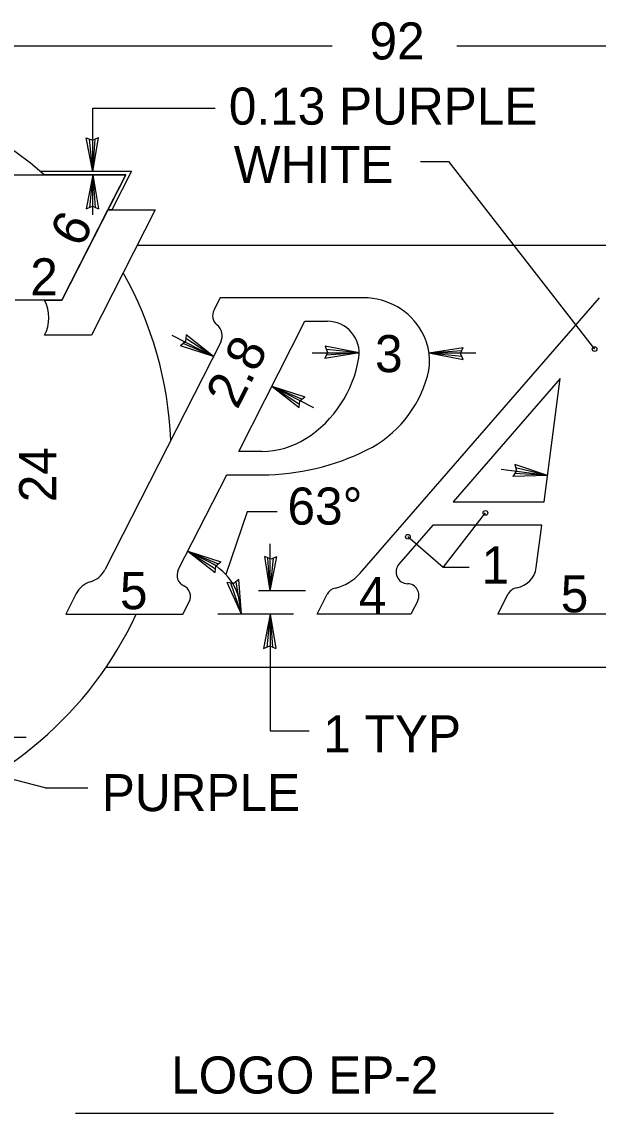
# Model space of a CAD drawing. Extents: x 10268197 to 10269179, y 2141503 to 2142677.
# Drawn here: x 10268694.59 to 10268707.32, y 2142243.22 to 2142267.31 of the extents above; entities that cross this region are included whole.
import ezdxf

# ---------------------------------------------------------------- set-up
doc = ezdxf.new("R2010")
doc.units = 0
for name, color, linetype in [('1', 7, 'Continuous'), ('21', 7, 'Continuous'), ('3', 7, 'Continuous'), ('52', 7, 'Continuous'), ('SOILS_SP83_SHP', 7, 'Continuous')]:
    doc.layers.add(name, color=color, linetype=linetype)

msp = doc.modelspace()

# ---------------------------------------------------------------- linework, layer by layer
at = {"layer": '1'}
for p, q in [((10268674.314, 2142266.783), (10268701.45, 2142266.783)), ((10268704.204, 2142266.783), (10268726.659, 2142266.783)), ((10268696.161, 2142265.407), (10268698.86, 2142265.407)), ((10268696.161, 2142264.037), (10268696.161, 2142265.407)), ((10268703.4, 2142264.229), (10268704.016, 2142264.229)), ((10268704.016, 2142264.229), (10268707.244, 2142260.089)), ((10268696.161, 2142263.052), (10268696.161, 2142263.944)), ((10268695.477, 2142261.168), (10268696.493, 2142263.161)), ((10268697.538, 2142263.161), (10268696.128, 2142260.394)), ((10268696.493, 2142263.161), (10268697.538, 2142263.161)), ((10268695.092, 2142261.168), (10268695.477, 2142261.168)), ((10268696.128, 2142260.394), (10268695.093, 2142260.394)), ((10268697.903, 2142260.398), (10268698.824, 2142259.928)), ((10268701.008, 2142260.005), (10268702.043, 2142260.005)), ((10268703.585, 2142260.005), (10268704.619, 2142260.005)), ((10268700.116, 2142259.271), (10268701.038, 2142258.801)), ((10268706.204, 2142257.297), (10268705.179, 2142257.431)), ((10268699.566, 2142256.498), (10268699.097, 2142255.114)), ((10268700.232, 2142256.498), (10268699.566, 2142256.498)), ((10268703.902, 2142255.268), (10268704.834, 2142256.475)), ((10268700.079, 2142254.752), (10268700.079, 2142255.787)), ((10268703.902, 2142255.268), (10268703.119, 2142255.946)), ((10268698.736, 2142255.388), (10268698.26, 2142255.63)), ((10268704.474, 2142255.268), (10268703.902, 2142255.268)), ((10268700.855, 2142254.752), (10268699.82, 2142254.752)), ((10268700.596, 2142254.235), (10268698.925, 2142254.235)), ((10268700.079, 2142254.235), (10268700.079, 2142251.663)), ((10268700.079, 2142251.663), (10268700.941, 2142251.663)), ((10268692.631, 2142251.519), (10268694.69, 2142251.519)), ((10268695.11, 2142250.402), (10268692.453, 2142251.097)), ((10268695.11, 2142250.402), (10268696.047, 2142250.402))]:
    msp.add_line(p, q, dxfattribs=at)
for centre in [(10268707.244, 2142260.089), (10268704.833, 2142256.474), (10268703.119, 2142255.945)]:
    msp.add_circle(centre, 0.0517, dxfattribs=at)
for centre, radius, start, end in [((10268694.36, 2142260.78), 0.828, 332.2089, 27.9127), ((10268698.148, 2142254.235), 1.294, 0, 62.9941)]:
    msp.add_arc(centre, radius, start, end, dxfattribs=at)
at = {"layer": '21'}
msp.add_line((10268695.781, 2142243.223), (10268706.336, 2142243.223), dxfattribs=at)
at = {"layer": '3'}
msp.add_lwpolyline([(10268694.997, 2142264.015), (10268697.014, 2142264.015), (10268696.579, 2142263.161), (10268696.493, 2142263.161), (10268696.888, 2142263.937), (10268695.087, 2142263.936)], close=True, dxfattribs=at)
at = {"layer": '52'}
for p, q in [((10268696.163, 2142264.001), (10268696.017, 2142264.752)), ((10268696.017, 2142264.752), (10268696.151, 2142264.697)), ((10268696.163, 2142264.001), (10268696.088, 2142264.724)), ((10268696.151, 2142264.697), (10268696.283, 2142264.757)), ((10268696.163, 2142264.001), (10268696.283, 2142264.757)), ((10268696.163, 2142264.001), (10268696.214, 2142264.725)), ((10268696.163, 2142263.939), (10268696.017, 2142263.187)), ((10268696.163, 2142263.939), (10268696.088, 2142263.216)), ((10268696.163, 2142263.939), (10268696.283, 2142263.182)), ((10268696.163, 2142263.939), (10268696.214, 2142263.215)), ((10268696.017, 2142263.187), (10268696.151, 2142263.242)), ((10268696.151, 2142263.242), (10268696.283, 2142263.182)), ((10268698.221, 2142260.4), (10268698.209, 2142260.255)), ((10268698.824, 2142259.928), (10268698.221, 2142260.4)), ((10268698.209, 2142260.255), (10268698.096, 2142260.164)), ((10268698.824, 2142259.928), (10268698.096, 2142260.164)), ((10268698.824, 2142259.928), (10268698.156, 2142260.212)), ((10268698.824, 2142259.928), (10268698.215, 2142260.324)), ((10268702.043, 2142260.005), (10268701.292, 2142260.151)), ((10268701.292, 2142260.151), (10268701.347, 2142260.017)), ((10268703.585, 2142260.005), (10268704.342, 2142260.124)), ((10268704.282, 2142259.993), (10268704.342, 2142260.124)), ((10268701.347, 2142260.017), (10268701.286, 2142259.884)), ((10268702.043, 2142260.005), (10268701.286, 2142259.884)), ((10268702.043, 2142260.005), (10268701.319, 2142259.954)), ((10268702.043, 2142260.005), (10268701.32, 2142260.08)), ((10268703.585, 2142260.005), (10268704.309, 2142260.055)), ((10268703.585, 2142260.005), (10268704.337, 2142259.859)), ((10268703.585, 2142260.005), (10268704.308, 2142259.929)), ((10268704.337, 2142259.859), (10268704.282, 2142259.993)), ((10268700.116, 2142259.271), (10268700.845, 2142259.035)), ((10268700.116, 2142259.271), (10268700.72, 2142258.799)), ((10268700.116, 2142259.271), (10268700.726, 2142258.875)), ((10268700.116, 2142259.271), (10268700.785, 2142258.987)), ((10268700.72, 2142258.799), (10268700.731, 2142258.944)), ((10268700.731, 2142258.944), (10268700.845, 2142259.035)), ((10268706.204, 2142257.297), (10268705.478, 2142257.539)), ((10268705.478, 2142257.539), (10268705.516, 2142257.399)), ((10268706.204, 2142257.297), (10268705.497, 2142257.465)), ((10268705.516, 2142257.399), (10268705.439, 2142257.276)), ((10268706.204, 2142257.297), (10268705.439, 2142257.276)), ((10268706.204, 2142257.297), (10268705.48, 2142257.34)), ((10268698.26, 2142255.63), (10268698.988, 2142255.393)), ((10268698.26, 2142255.63), (10268698.864, 2142255.158)), ((10268698.26, 2142255.63), (10268698.87, 2142255.235)), ((10268698.26, 2142255.63), (10268698.928, 2142255.346)), ((10268698.864, 2142255.158), (10268698.874, 2142255.303)), ((10268698.874, 2142255.303), (10268698.988, 2142255.393)), ((10268700.079, 2142254.752), (10268699.959, 2142255.509)), ((10268700.091, 2142255.449), (10268699.959, 2142255.509)), ((10268700.079, 2142254.752), (10268700.028, 2142255.477)), ((10268700.079, 2142254.752), (10268700.225, 2142255.505)), ((10268700.079, 2142254.752), (10268700.154, 2142255.476)), ((10268700.225, 2142255.505), (10268700.091, 2142255.449)), ((10268699.442, 2142254.235), (10268699.13, 2142254.936)), ((10268699.273, 2142254.911), (10268699.13, 2142254.936)), ((10268699.442, 2142254.235), (10268699.206, 2142254.922)), ((10268699.388, 2142255), (10268699.273, 2142254.911)), ((10268699.442, 2142254.235), (10268699.328, 2142254.953)), ((10268699.442, 2142254.235), (10268699.388, 2142255)), ((10268700.079, 2142254.235), (10268699.933, 2142253.483)), ((10268700.079, 2142254.235), (10268700.003, 2142253.512)), ((10268700.079, 2142254.235), (10268700.199, 2142253.478)), ((10268700.079, 2142254.235), (10268700.13, 2142253.51)), ((10268699.933, 2142253.483), (10268700.067, 2142253.539)), ((10268700.067, 2142253.539), (10268700.199, 2142253.478))]:
    msp.add_line(p, q, dxfattribs=at)
at = {"layer": 'SOILS_SP83_SHP'}
for p, q in [((10268694.997, 2142264.015), (10268697.014, 2142264.015)), ((10268697.014, 2142264.015), (10268696.579, 2142263.161)), ((10268688.091, 2142263.937), (10268696.888, 2142263.937)), ((10268696.888, 2142263.937), (10268695.479, 2142261.171)), ((10268695.477, 2142261.168), (10268696.493, 2142263.161)), ((10268697.538, 2142263.161), (10268696.128, 2142260.394)), ((10268696.493, 2142263.161), (10268697.538, 2142263.161)), ((10268697.142, 2142262.385), (10268726.659, 2142262.385)), ((10268695.479, 2142261.171), (10268694.443, 2142261.171)), ((10268695.092, 2142261.168), (10268695.477, 2142261.168)), ((10268698.976, 2142261.22), (10268698.835, 2142260.945)), ((10268702.145, 2142261.22), (10268698.976, 2142261.22)), ((10268702.066, 2142255.144), (10268707.349, 2142261.22)), ((10268699.382, 2142257.831), (10268700.846, 2142260.703)), ((10268700.846, 2142260.703), (10268701.345, 2142260.703)), ((10268696.128, 2142260.394), (10268695.093, 2142260.394)), ((10268698.985, 2142260.242), (10268696.423, 2142255.215)), ((10268706.483, 2142259.436), (10268704.121, 2142256.719)), ((10268706.129, 2142256.719), (10268706.483, 2142259.436)), ((10268699.895, 2142257.831), (10268699.382, 2142257.831)), ((10268698.048, 2142255.215), (10268699.118, 2142257.314)), ((10268699.118, 2142257.314), (10268699.895, 2142257.314)), ((10268704.121, 2142256.719), (10268706.129, 2142256.719)), ((10268703.672, 2142256.201), (10268702.922, 2142255.339)), ((10268706.077, 2142256.201), (10268703.672, 2142256.201)), ((10268705.954, 2142255.266), (10268706.077, 2142256.201)), ((10268695.794, 2142254.692), (10268695.562, 2142254.235)), ((10268701.114, 2142254.235), (10268701.339, 2142254.678)), ((10268705.107, 2142254.235), (10268705.335, 2142254.684)), ((10268698.149, 2142254.235), (10268698.289, 2142254.512)), ((10268703.336, 2142254.534), (10268703.183, 2142254.235)), ((10268695.562, 2142254.235), (10268698.149, 2142254.235)), ((10268703.183, 2142254.235), (10268701.114, 2142254.235)), ((10268707.694, 2142254.235), (10268705.107, 2142254.235)), ((10268696.456, 2142253.071), (10268721.913, 2142253.071))]:
    msp.add_line(p, q, dxfattribs=at)
for centre, radius, start, end in [((10268689.611, 2142257.727), 8.279, 48.5904, 217.4727), ((10268689.611, 2142257.727), 8.279, 2.4236, 29.2771), ((10268694.36, 2142260.78), 0.828, 332.2089, 27.9127), ((10268702.145, 2142259.745), 1.475, 29.4315, 90), ((10268699.065, 2142260.826), 0.259, 152.9784, 231.1602), ((10268698.708, 2142260.383), 0.31, 333.0027, 51.1602), ((10268701.344, 2142260.004), 0.699, 351.076, 90), ((10268702.303, 2142259.834), 1.294, 344.7074, 29.4315), ((10268699.478, 2142260.297), 2.587, 302.4206, 351.076), ((10268701.055, 2142260.175), 2.587, 296.6431, 344.7074), ((10268699.895, 2142259.642), 1.811, 270, 302.4206), ((10268699.895, 2142262.488), 5.174, 270, 296.6431), ((10268703.117, 2142255.168), 0.259, 138.9824, 268.6869), ((10268695.962, 2142255.448), 0.517, 286.4317, 332.9959), ((10268698.279, 2142255.097), 0.259, 152.9884, 244.7832), ((10268701.285, 2142255.822), 1.035, 282.7162, 318.9966), ((10268705.441, 2142255.332), 0.517, 279.2397, 352.5632), ((10268696.255, 2142254.456), 0.517, 106.4317, 152.9742), ((10268698.058, 2142254.628), 0.259, 333.0239, 64.7832), ((10268701.569, 2142254.56), 0.259, 102.7162, 153.0239), ((10268703.105, 2142254.651), 0.259, 332.9784, 88.6869), ((10268705.566, 2142254.566), 0.259, 99.2397, 153.0239), ((10268689.611, 2142257.727), 8.279, 237.5383, 335.047)]:
    msp.add_arc(centre, radius, start, end, dxfattribs=at)

# ---------------------------------------------------------------- texts
at = {"layer": '1'}
for s, height, p in [('92', 0.8187, (10268702.271, 2142266.482)), ('0.13 PURPLE', 0.81867, (10268699.165, 2142265.043)), ('WHITE', 0.8187, (10268699.273, 2142263.756)), ('2', 0.819, (10268694.779, 2142261.274)), ('3', 0.819, (10268702.394, 2142259.579)), ('63°', 0.8187, (10268700.46, 2142256.214)), ('1', 0.819, (10268704.744, 2142254.913)), ('5', 0.819, (10268696.76, 2142254.347)), ('4', 0.819, (10268702.034, 2142254.241)), ('5', 0.819, (10268706.495, 2142254.278)), ('1 TYP', 0.8187, (10268701.251, 2142251.187)), ('PURPLE', 0.8187, (10268696.359, 2142249.889)), ('LOGO EP-2', 0.8187, (10268697.89, 2142243.655))]:
    msp.add_text(s, height=height, dxfattribs=at).set_placement(p)
for s, height, rotation, p in [('6', 0.819, 63, (10268695.909, 2142262.298)), ('2.8', 0.8187, 62.9907, (10268699.351, 2142258.734)), ('24', 0.8187, 90, (10268695.351, 2142256.708))]:
    msp.add_text(s, height=height, rotation=rotation, dxfattribs=at).set_placement(p)

doc.saveas('drawing.dxf')
